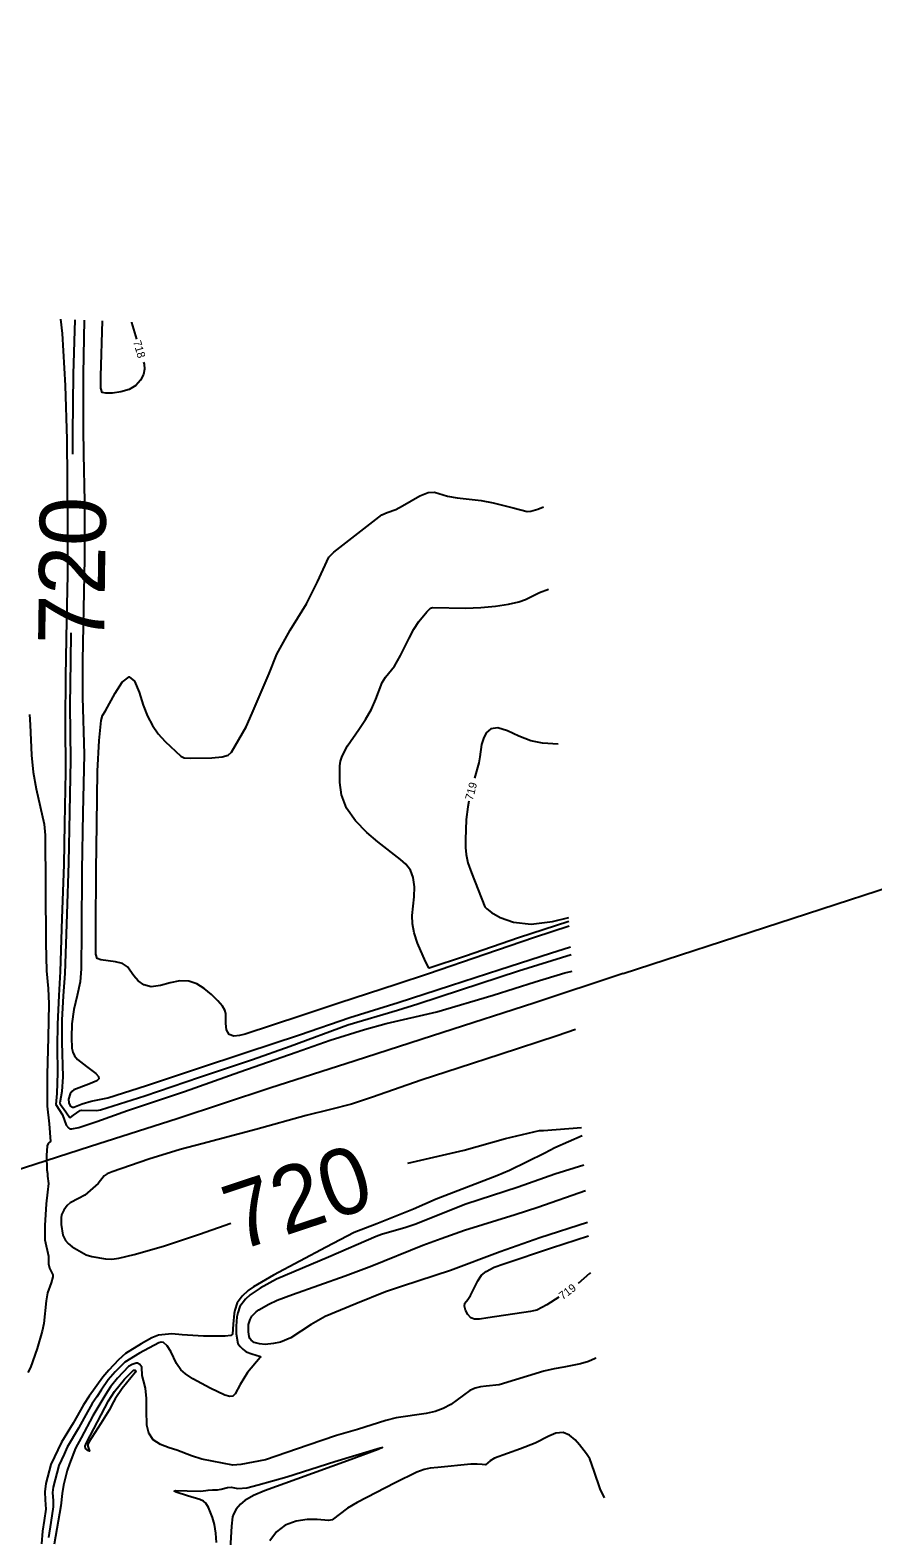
# Model space of a CAD drawing. Extents: x -310467766 to 17062430, y -322263100 to 8322522.
# Drawn here: x 1395749 to 1396171, y 573612 to 574364 of the extents above; entities that cross this region are included whole.
import ezdxf

# ---------------------------------------------------------------- set-up
doc = ezdxf.new("R2010")
doc.units = 0
for name, color, linetype in [('DT_X_Contour_Minor', 7, 'Continuous'), ('Level 14', 7, 'Continuous'), ('Level 19', 7, 'Continuous')]:
    doc.layers.add(name, color=color, linetype=linetype)

msp = doc.modelspace()

# ---------------------------------------------------------------- linework, layer by layer
at = {"layer": 'DT_X_Contour_Minor'}
for points in [[(1395764.48, 574219.92), (1395765.21, 574212.65), (1395766.71, 574186.76), (1395767.65, 574159.75), (1395767.76, 574139.98), (1395767.89, 574112.78), (1395767.89, 574092.04), (1395767.41, 574069.22), (1395766.9, 574041.38), (1395766.83, 574018.07), (1395766.89, 573993.61), (1395766.51, 573967.52), (1395766.09, 573947.31), (1395765.02, 573920.19), (1395764.28, 573893.78), (1395763.61, 573881.78), (1395762.86, 573867.44), (1395762.69, 573856.18), (1395762.96, 573843.17), (1395762.63, 573832.87), (1395762.04, 573827.21), (1395765.36, 573822.06), (1395767.27, 573816.95), (1395768.52, 573815.41), (1395769.14, 573815.14), (1395770.06, 573815.1), (1395773.52, 573815.85), (1395782.64, 573818.76), (1395797.96, 573824.29), (1395826.41, 573833.85), (1395854.05, 573843.6), (1395882.29, 573853.4), (1395899.3, 573859.38), (1395916.34, 573864.76), (1395927.3, 573867.73), (1395952.61, 573873.67), (1395980.74, 573881.88), (1396001.76, 573888.59), (1396016.61, 573893.15), (1396020.15, 573893.98)], [(1395776.34, 574219.42), (1395775.84, 574192.51), (1395775.79, 574165.16), (1395775.88, 574152.43), (1395776.41, 574128.79), (1395776.49, 574100.03), (1395775.98, 574075.29), (1395775.49, 574049.14), (1395775.51, 574030.91), (1395776.21, 574002.18), (1395775.6, 573973.05), (1395775.16, 573944.41), (1395774.99, 573914.1), (1395774.82, 573895.18), (1395774.24, 573888.59), (1395772.79, 573881.86), (1395771.17, 573874.71), (1395770.11, 573867.63), (1395769.92, 573860.84), (1395770.17, 573855.47), (1395770.58, 573853.41), (1395771.47, 573851.57), (1395773.01, 573849.82), (1395777.48, 573846.34), (1395782.17, 573842.85), (1395783.49, 573841.36), (1395783.57, 573840.16), (1395782.59, 573839.2), (1395778.67, 573837.47), (1395771.07, 573834.68), (1395770.04, 573833.81), (1395769.25, 573832.59), (1395768.41, 573829.91), (1395768.54, 573828.06), (1395769.33, 573826.7), (1395770.44, 573825.88), (1395771.07, 573825.95), (1395775.32, 573827.66), (1395779.73, 573828.96), (1395788.04, 573830.6), (1395807.48, 573836.85), (1395832.37, 573845.1), (1395857.09, 573853.22), (1395883.84, 573862.07), (1395909, 573870.82), (1395933.28, 573878.34), (1395959.35, 573886.83), (1395984.05, 573894.85), (1396009.3, 573902.89), (1396019.4, 573906.14)], [(1395771.63, 574219.62), (1395770.84, 574192.42), (1395770.49, 574162.66), (1395770.43, 574152.34)], [(1395805.87, 574198.42), (1395806.22, 574197.32), (1395806.42, 574194.91), (1395805.94, 574192.24), (1395804.48, 574189.43), (1395802.05, 574186.8), (1395798.69, 574184.74), (1395794.59, 574183.52), (1395790.47, 574182.96), (1395787.17, 574182.83), (1395785.31, 574183.19), (1395784.64, 574185.45), (1395784.67, 574191.36), (1395785.48, 574219.04)], [(1395799.94, 574218.44), (1395800.01, 574218.28), (1395802.42, 574209.91)], [(1396018.76, 573916.49), (1396001.39, 573910.76), (1395976.52, 573902.21), (1395948.42, 573892.55), (1395932.24, 573887.29), (1395903.99, 573878.06), (1395884.54, 573871.54), (1395856.81, 573862.43), (1395853.98, 573861.72), (1395851.03, 573861.46), (1395848.68, 573862.3), (1395847.43, 573864.63), (1395847.05, 573867.74), (1395847.06, 573872.8), (1395846.62, 573874.49), (1395845.37, 573876.46), (1395843.04, 573879.19), (1395839.89, 573882.33), (1395836.29, 573885.3), (1395832.53, 573887.6), (1395828.54, 573888.95), (1395824.15, 573889.12), (1395819.3, 573888.12), (1395814.36, 573886.79), (1395809.83, 573886.18), (1395806.1, 573887.07), (1395803.19, 573889.1), (1395801.04, 573891.61), (1395797.87, 573896.14), (1395795.49, 573897.72), (1395791.9, 573898.68), (1395784.56, 573899.6), (1395782.72, 573900.28), (1395782.05, 573902.36), (1395782.04, 573915.26), (1395782.29, 573944.64), (1395782.63, 573967.44), (1395782.89, 573994), (1395783.78, 574009.19), (1395784.71, 574019.33), (1395785.45, 574021.79), (1395786.96, 574024.05), (1395791.8, 574032.97), (1395795.34, 574038.44), (1395798.76, 574041.07), (1395801.51, 574038.91), (1395803.75, 574033.44), (1395805.79, 574026.97), (1395807.93, 574021.36), (1395810.36, 574016.68), (1395813.29, 574012.57), (1395816.74, 574008.76), (1395824.67, 574001.4), (1395826.33, 574000.67), (1395829.25, 574000.42), (1395840.1, 574000.63), (1395845.17, 574001.13), (1395848.2, 574002), (1395849.84, 574003.43), (1395857.21, 574016.11), (1395860.2, 574022.87), (1395864.23, 574032.27), (1395868.81, 574042.69), (1395872.52, 574052.43), (1395879.23, 574064.45), (1395883.1, 574070.56), (1395887.38, 574077.54), (1395892.86, 574088.62), (1395898.65, 574100.91), (1395901.15, 574103.34), (1395914.63, 574113.83), (1395925.02, 574122.04), (1395927.81, 574123.23), (1395932, 574124.78), (1395935.32, 574126.51), (1395944.1, 574131.62), (1395948.21, 574133.3), (1395951.4, 574133.44), (1395957.86, 574131.38), (1395962.7, 574130.59), (1395974.71, 574129.27), (1395980.75, 574128.15), (1395990.72, 574125.57), (1395997.7, 574123.75), (1395999.54, 574123.85), (1396003.1, 574124.97), (1396005.86, 574126.07)], [(1396018.62, 573918.81), (1395993.45, 573910.64), (1395966.81, 573901.48), (1395948.77, 573895.38), (1395948.58, 573895.56), (1395946.97, 573898.74), (1395942.89, 573907.91), (1395941.15, 573913.1), (1395940.34, 573917.62), (1395940.3, 573921.78), (1395941.16, 573931.08), (1395941.32, 573936.16), (1395940.79, 573940.76), (1395939.32, 573944.44), (1395937.06, 573947.36), (1395934.32, 573949.83), (1395923.08, 573958.54), (1395917.52, 573963.31), (1395911.89, 573969.06), (1395907.4, 573975.45), (1395904.92, 573982.07), (1395904.03, 573988.25), (1395904.06, 573996.6), (1395904.37, 573998.87), (1395905.03, 574000.9), (1395906.19, 574003.38), (1395907.95, 574006.51), (1395913.51, 574014.81), (1395916.85, 574019.75), (1395919.83, 574024.87), (1395922.07, 574029.89), (1395925.28, 574038.23), (1395926.9, 574040.97), (1395931.43, 574046.46), (1395934.32, 574051.78), (1395938.65, 574060.49), (1395941.13, 574064.95), (1395943.56, 574068.71), (1395947.53, 574073.66), (1395949.42, 574075.43), (1395950.33, 574075.7), (1395966.9, 574075.45), (1395974.53, 574075.73), (1395981.91, 574076.41), (1395988.42, 574077.4), (1395993.49, 574078.56), (1395996.81, 574079.76), (1396003.87, 574083.29), (1396008.39, 574084.95)], [(1395769.64, 574063.1), (1395769.38, 574048.96), (1395769.15, 574026.78), (1395769.46, 573999.62), (1395768.88, 573973.42), (1395768.36, 573948.18), (1395767.52, 573922.46), (1395766.65, 573892.73), (1395765.83, 573881.56), (1395765.09, 573869.39), (1395765.08, 573858.49), (1395765.52, 573841.1), (1395765.14, 573833.75), (1395764.07, 573828.13), (1395764.3, 573827.39), (1395765.9, 573825.21), (1395769.01, 573821.03), (1395769.42, 573820.85), (1395770.99, 573821.94), (1395774.25, 573824.23), (1395775.17, 573824.44), (1395782.38, 573824.22), (1395784.41, 573824.62), (1395806.66, 573831.68), (1395833.88, 573840.89), (1395860.35, 573849.86), (1395879.28, 573856.47), (1395908.06, 573867.18), (1395932.82, 573874.49), (1395943.04, 573877.65), (1395964.37, 573884.69), (1395993.33, 573894.06), (1396019.63, 573902.34)], [(1395748.91, 574022.29), (1395749.28, 574017.14), (1395749.87, 574001.98), (1395750.71, 573993.36), (1395752.2, 573985.05), (1395756.34, 573967.42), (1395756.75, 573961.93), (1395756.99, 573935.72), (1395757.12, 573907.96), (1395757.45, 573894.13), (1395758.31, 573885.34), (1395758.6, 573877.57), (1395758.26, 573860.71), (1395757.78, 573842.22), (1395757.73, 573826.43), (1395758.69, 573817.57), (1395759.51, 573808.75), (1395758.74, 573808.27), (1395758.21, 573807.82), (1395757.78, 573806.67), (1395757.46, 573801.84), (1395757.59, 573794.65), (1395757.87, 573792.77), (1395757.96, 573791.39), (1395758.36, 573787.76), (1395757.96, 573783.45), (1395757.34, 573777.57)], [(1396013.17, 574007.36), (1396005.39, 574007.98), (1395999.6, 574009.13), (1395993.59, 574011.48), (1395987.9, 574014.07), (1395983.09, 574015.6), (1395979.61, 574015.13), (1395977.29, 574013.07), (1395975.82, 574010.2), (1395974.93, 574007.2), (1395974.05, 574001.05), (1395973.51, 573998.08), (1395971.46, 573990.5)], [(1395968.57, 573978.85), (1395968.01, 573976.16), (1395967.2, 573969.78), (1395966.83, 573959.61), (1395966.84, 573955.8), (1395967.16, 573952.21), (1395968.1, 573948.11), (1395969.83, 573943.02), (1395976.58, 573926.07), (1395977.51, 573925.03), (1395979.86, 573923.32), (1395984.29, 573920.78), (1395990.92, 573918.38), (1395999.75, 573917.4), (1396010.41, 573918.69), (1396018.5, 573920.81)], [(1396021.94, 573864.85), (1396012.77, 573861.61), (1395984.21, 573852.3), (1395963.69, 573845.65), (1395944.65, 573839.48), (1395920.37, 573830.93), (1395909.97, 573827.41), (1395899.42, 573824.8), (1395887.19, 573821.84), (1395862.12, 573814.72), (1395835.02, 573807.66), (1395824.25, 573804.81), (1395808.51, 573799.98), (1395790.24, 573793.65), (1395787.73, 573792.56), (1395786.31, 573791.61), (1395783.26, 573787.83), (1395776.63, 573781.92), (1395773.47, 573780.28), (1395769.26, 573778.18), (1395767.71, 573776.83), (1395766.15, 573774.5), (1395764.92, 573772.15), (1395764.71, 573770.67), (1395764.76, 573767.27), (1395765.59, 573761.9), (1395766.89, 573759.35), (1395768.21, 573757.73), (1395770.33, 573756.1), (1395777.35, 573752.06), (1395780.16, 573751.22), (1395786.92, 573750.13), (1395790.13, 573750.03), (1395793.58, 573750.42), (1395801.27, 573752.27), (1395815.93, 573756.54), (1395833.96, 573762.41), (1395849.56, 573767.92)], [(1395938.14, 573797.99), (1395966.19, 573804.52), (1395986.82, 573810.22), (1396003.88, 573814.35), (1396005.82, 573814.37), (1396024.96, 573815.82)], [(1396025.22, 573811.62), (1396011.56, 573805.64), (1396006.61, 573803.01), (1395988.83, 573794.26), (1395982.53, 573791.58), (1395952.25, 573780.02), (1395940.9, 573774.95), (1395922.49, 573767.65), (1395911.31, 573763.32), (1395897.26, 573755.94), (1395870.96, 573742.04), (1395860.9, 573736.14), (1395858.17, 573734.25), (1395855.3, 573731.4), (1395852.81, 573728.12), (1395851.58, 573724.46), (1395851.19, 573722.83), (1395850.69, 573717.45), (1395850.5, 573712.42), (1395849.56, 573711.85), (1395846.83, 573711.46), (1395836, 573711.55), (1395825.19, 573712.14), (1395820.17, 573712.71), (1395813.35, 573712.02), (1395810.12, 573710.6), (1395804.7, 573707.69), (1395797.01, 573702.73), (1395793.51, 573699.62), (1395788.57, 573694.52), (1395785.62, 573691.01), (1395778.79, 573681.4), (1395776.01, 573677.11), (1395770.78, 573668.05), (1395765, 573658.54), (1395759.57, 573647.39), (1395757.18, 573637.88), (1395756.6, 573633.58), (1395756.83, 573629.66), (1395757.04, 573624.91), (1395756.31, 573619.26), (1395755.48, 573614.06), (1395754.93, 573607.64)], [(1396026.12, 573796.95), (1396011.53, 573792.49), (1395993.29, 573785.93), (1395967.13, 573777.43), (1395941.58, 573767.37), (1395937, 573765.72), (1395924.94, 573762.24), (1395922.23, 573761.22), (1395898.33, 573751.03), (1395872.39, 573739.94), (1395864.3, 573735.46), (1395859.27, 573732.22), (1395856.88, 573729.93), (1395854.15, 573726.37), (1395853.01, 573723.12), (1395852.6, 573721.16), (1395852.24, 573716.41), (1395852.3, 573712.6), (1395853.01, 573707.84), (1395854.22, 573706.23), (1395855.5, 573705.02), (1395857.25, 573703.71), (1395860.1, 573702.64), (1395864.42, 573701.36), (1395864.3, 573700.8), (1395857.99, 573693.23), (1395854.3, 573687.27), (1395851.69, 573682.59), (1395850.62, 573681.5), (1395849.04, 573681.33), (1395846.55, 573682.06), (1395839.21, 573685.52), (1395830.52, 573690.22), (1395826.95, 573692.57), (1395824.53, 573694.71), (1395822.35, 573697.84), (1395819.62, 573703.89), (1395817.73, 573706.68), (1395815.95, 573708.3), (1395814.74, 573708.53), (1395813.61, 573708.15), (1395803.9, 573703.02), (1395796.57, 573698.5), (1395791.76, 573693.6), (1395788.26, 573689.57), (1395784.8, 573684.44), (1395782.54, 573681.2), (1395780.22, 573677.81), (1395776.34, 573670.65), (1395773.48, 573665.48), (1395767.74, 573655.95), (1395766.19, 573652.5), (1395763.6, 573646.75), (1395760.7, 573635.94), (1395760.52, 573633.3), (1395760.85, 573629.21), (1395760.76, 573626.16), (1395759.6, 573618.3), (1395758.37, 573610.76)], [(1396027.89, 573768.34), (1396003.99, 573760.6), (1395984.25, 573753.64), (1395959.31, 573744.22), (1395935.39, 573736.5), (1395926.98, 573733.6), (1395912.06, 573727.7), (1395896.72, 573721.33), (1395889.7, 573717.24), (1395879.62, 573710.61), (1395874.33, 573708.46), (1395870.9, 573707.83), (1395866.73, 573707.32), (1395863.98, 573707.63), (1395861.22, 573708.27), (1395859.78, 573709.45), (1395859.12, 573710.25), (1395858.67, 573711.39), (1395858.34, 573713.61), (1395858.43, 573717.31), (1395859.19, 573719.76), (1395860.06, 573721.43), (1395862.25, 573723.59), (1395863.6, 573724.63), (1395868.61, 573727.54), (1395872.82, 573729.53), (1395880.4, 573732.31), (1395906.69, 573741.59), (1395920.11, 573746.67), (1395945.58, 573757.02), (1395954.78, 573760.24), (1395966.36, 573764.39), (1395991.66, 573772.3), (1396002.98, 573776.03), (1396026.91, 573784.22)], [(1395757.34, 573777.57), (1395756.67, 573766.77)], [(1395756.67, 573766.77), (1395756.64, 573759.67), (1395758.49, 573751.46), (1395758.39, 573747.58), (1395758.95, 573745.53), (1395760.62, 573742.06), (1395760.6, 573741.09), (1395759.79, 573738.2), (1395757.99, 573733.11), (1395757.27, 573729.08), (1395756.17, 573717.79), (1395755.35, 573713.97), (1395752.7, 573705.23), (1395749.37, 573695.74), (1395748.14, 573693.33)], [(1396013.47, 573730.89), (1396007.58, 573727.06), (1396002.53, 573724.52), (1396000.91, 573724.09), (1395999.4, 573723.73), (1395977.98, 573720.62), (1395973.95, 573720.05), (1395971.33, 573720), (1395969.51, 573720.72), (1395968.04, 573722.34), (1395966.97, 573724.41), (1395966.46, 573726.41), (1395966.62, 573727.89), (1395968, 573729.79), (1395969.39, 573731.83), (1395973.02, 573739.21), (1395974.96, 573741.91), (1395977.22, 573743.88), (1395981.23, 573745.9), (1395985.98, 573747.6), (1396009.87, 573755.69), (1396028.3, 573761.66)], [(1396029.44, 573743.06), (1396028.84, 573742.72), (1396023.23, 573737.88)], [(1396032.06, 573700.61), (1396031.64, 573700.31), (1396028.31, 573698.76), (1396024.45, 573697.57), (1396015.97, 573695.96), (1396011.29, 573695.15), (1396005.98, 573693.9), (1395983.64, 573687.16), (1395977.18, 573686.43), (1395974.45, 573686.14), (1395971.79, 573685.51), (1395969.07, 573684.25), (1395959.6, 573677.32), (1395955.81, 573675.33), (1395951.66, 573673.83), (1395947.15, 573672.79), (1395932.16, 573670.7), (1395927.08, 573669.35), (1395912.93, 573664.83), (1395902.4, 573661.83), (1395888.29, 573657.04), (1395866.95, 573649.72), (1395854.51, 573647.39), (1395850.58, 573646.98), (1395835.16, 573649.98), (1395829.93, 573651.65), (1395822.62, 573654.44), (1395818.78, 573655.57), (1395814.47, 573657.24), (1395810.8, 573659.69), (1395808.62, 573663.03), (1395807.67, 573666.9), (1395807.44, 573674.33), (1395807.5, 573680.39), (1395807.01, 573685.52), (1395806.01, 573689.29), (1395805.21, 573691.86), (1395805.05, 573695.94), (1395804.1, 573697.26), (1395802.98, 573697.97), (1395802.23, 573697.99), (1395800.31, 573697.36), (1395798.51, 573696.33), (1395792.93, 573690.53), (1395789.47, 573686.17), (1395787.03, 573682.47), (1395780.62, 573671.7), (1395774.75, 573660.67), (1395771.95, 573655.5), (1395768.99, 573647.65), (1395767.85, 573644.31), (1395766, 573637.07), (1395765.21, 573632.86), (1395764.61, 573626.72), (1395761.27, 573607.47)], [(1395790.85, 573678.63), (1395788.79, 573674.49), (1395784.66, 573667.79), (1395778.57, 573658.41), (1395778.1, 573657.28), (1395778.18, 573656.46), (1395778.9, 573654.04), (1395778.4, 573654.11), (1395776.99, 573655.32), (1395776.73, 573656.54), (1395777.5, 573658.23), (1395788.48, 573679.17), (1395791.39, 573683.76), (1395796.45, 573689.98), (1395800.89, 573694.44), (1395801.73, 573694.52), (1395802.05, 573694.11), (1395801.68, 573693.37), (1395795.32, 573685.35), (1395791.74, 573680.14), (1395790.85, 573678.63)], [(1396036.37, 573630.62), (1396034.27, 573635.12), (1396031.29, 573644.02), (1396029.11, 573650.15), (1396027.43, 573652.64), (1396023.92, 573657.13), (1396021.7, 573659.62), (1396018.89, 573661.96), (1396015.65, 573663.26), (1396012.12, 573662.95), (1396008.5, 573661.49), (1396001.72, 573658.03), (1395994.46, 573655.13), (1395981.46, 573650.41), (1395979.26, 573649.16), (1395976.85, 573647.22), (1395975.16, 573647.24), (1395972.66, 573647.55), (1395969.53, 573647.46), (1395953.04, 573645.87), (1395949.21, 573645.45), (1395946.16, 573644.82), (1395942.63, 573643.52), (1395931.65, 573638.2), (1395912.79, 573628.39), (1395907.97, 573625.48), (1395900.17, 573619.68), (1395898.38, 573619.31), (1395892.69, 573619.79), (1395887.82, 573619.76), (1395882.2, 573618.98), (1395876.8, 573617.07), (1395872.42, 573613.73), (1395869.12, 573609.24)], [(1395842.45, 573608.4), (1395842.02, 573613.01), (1395841.36, 573617.3), (1395840.43, 573620.88), (1395838.4, 573625.77), (1395837.05, 573628.04), (1395835.89, 573629.06), (1395834.09, 573629.86), (1395827.89, 573631.71), (1395822.26, 573633.5), (1395821.25, 573634.06), (1395821.88, 573634.31), (1395827.79, 573634.13), (1395834.57, 573634.03), (1395838.3, 573634.56), (1395840.5, 573634.69), (1395842.86, 573634.63), (1395844.8, 573635.03), (1395847.87, 573635.87), (1395849.73, 573635.93), (1395853.1, 573635.33), (1395857.65, 573635.7), (1395863.26, 573637.11), (1395877.63, 573641.23), (1395901.53, 573648.87), (1395924.18, 573655.68), (1395925.35, 573655.81), (1395923.25, 573654.84), (1395907.93, 573649.07), (1395882.64, 573639.96), (1395866.41, 573634.22), (1395860.85, 573631.89), (1395856.5, 573629.33), (1395854.38, 573627.44), (1395852.29, 573624.99), (1395850.85, 573622.42), (1395850.45, 573621.08), (1395849.99, 573616.55), (1395849.07, 573602.27)]]:
    msp.add_lwpolyline(points, dxfattribs=at)
at = {"layer": 'Level 14'}
for points in [[(1396045.69, 573892.73), (1398068.94, 574551.49), (1399780.87, 575107.64), (1401168.4, 575558.39)], [(1396045.69, 573892.73), (1396001.03, 573878.02), (1395955.53, 573863.35), (1395911.76, 573849.15), (1395869, 573835.4), (1395822.72, 573820.18), (1395779.38, 573806.32), (1395701.9, 573781.33), (1395656.33, 573766.51), (1395613.86, 573752.89), (1395565.14, 573737), (1395519.21, 573722.15), (1395469.52, 573705.79), (1395427.26, 573692.2)]]:
    msp.add_lwpolyline(points, dxfattribs=at)

# ---------------------------------------------------------------- texts
at = {"layer": 'Level 19'}
for s, height, rotation, p in [('718', 4, 286.11221, (1395800.71, 574208.63)), ('720', 33, 89.16942, (1395786.19, 574057.18)), ('719', 4, 74.88558, (1395970.45, 573979.11)), ('720', 33, 18.32892, (1395853.07, 573753.82)), ('719', 4, 36.90421, (1396015.46, 573729.47))]:
    msp.add_text(s, height=height, rotation=rotation, dxfattribs=at).set_placement(p)

doc.saveas('drawing.dxf')
